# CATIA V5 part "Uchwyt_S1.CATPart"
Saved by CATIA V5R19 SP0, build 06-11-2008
Part number: Uchwyt
Bounding box of the stored display mesh (mm): x -86.292 to 86.292, y -95 to 79, z 0 to 116
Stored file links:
  G:\Catia\CD\Ustawienia\Uchwyt\Uchwyt_S1.CATPart
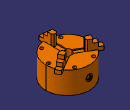
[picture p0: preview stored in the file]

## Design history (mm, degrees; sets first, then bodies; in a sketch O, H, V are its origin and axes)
Parameters
  Rozstaw = 45 mm
Body1 (main body)
  Sketch1 on xy-plane, origin (0, 0, 0), H (1, 0, 0), V (0, 1, 0)
    circle A1 centre (0, 0) radius 79
    circle A2 centre (0, 0) radius 16
    radius A1 = 79
    radius A2 = 16
  Pad1: profile Sketch1, direction (0, 0, 1), length 80
  Sketch2 on end face of Pad1, origin (55.5929, -45.085, 80), H (1, 0, 0), V (0, 1, 0)
    point P1 (-21.2096, -14.6017)
    construction line L1 (-55.5929, 134.677) -> (-55.5929, -51.2454)
    reference intersected line E1 through (-55.5929, 0) direction (0, 1) from yz-plane
    construction line L2 (-55.5929, 44.9521) -> (-10.3181, -33.4663)
    point P4 (-55.5929, 44.9521)
    angle L2 L1 = 30
    vertical: L1 V
    coincidence: E1 L1, P4 L1, P1 L2
  Hole1: placed by Sketch2, at (34.3834, -59.6867, 80) direction (0, 0, -1), diameter 8, through (limit type 6), counterbore diameter 12, counterbore depth 10
  CircPattern1: of Hole1, instances 6, angular step 60 {= 360.0*1 deg/CircPattern1.AngularNumber}, axis from end face of Pad1
  Sketch3 on end face of Pad1, origin (0, 0, 80), H (1, 0, 0), V (0, 1, 0)
    line L1 (-9, -8.5652) -> (9, -8.5652)
    line L2 (9, -8.5652) -> (9, -94.3558)
    line L3 (9, -94.3558) -> (-9, -94.3558)
    line L4 (-9, -94.3558) -> (-9, -8.5652)
    distance L4 L2 = 18
    distance L2 V = 9
    horizontal: L1 H, L3 H
    vertical: L2 V, L4 V
  Pocket1: profile Sketch3, direction (0, 0, -1), length 4
  CircPattern2: of Pocket1, instances 3, angular step 120 {= 360.0*1 deg/CircPattern2.AngularNumber}, axis from end face of Pad1
  Plane1: type Offset, Offset 79, RefPlane zx-plane
  Sketch4 on Plane1, origin (0, 79, 0), H (-1, 0, 0), V (0, 0, 1)
    circle A1 centre (0, 40) radius 8
    point P1 (0, 40)
    reference projected line E1 through (0, 0) direction (0, 1) from axis of face of Pad1 from Sketch1.A1
    distance A1 E1 = 8
    coincidence: P1 V
  Pocket2: profile Sketch4, direction (0, -1, 0), length 3
  Sketch5 on Plane1, origin (0, 79, 0), H (-1, 0, 0), V (0, 0, 1)
    circle A1 centre (0, 40) radius 12
    point P1 (0, 40)
    reference projected line E1 through (0, 0) direction (0, 1) from axis of face of Pad1 from Sketch1.A1
    distance A1 E1 = 12
    coincidence: P1 V
  Pocket3: profile Sketch5, direction (0, -1, 0), length 2
  Sketch6 on end face of Pocket2, origin (0, 76, 0), H (-1, 0, 0), V (0, 0, 1)
    point P1 (0, 40)
    point P2 (-4.348, 34.4178)
    point P3 (2.6603, 33.4434)
    point P4 (7.0083, 39.0256)
    point P5 (4.348, 45.5822)
    point P6 (-2.6603, 46.5566)
    point P7 (-7.0083, 40.9744)
    point P8 (-0.8438, 33.9306)
    line L1 (-4.348, 34.4178) -> (2.6603, 33.4434)
    line L2 (2.6603, 33.4434) -> (7.0083, 39.0256)
    line L3 (7.0083, 39.0256) -> (4.348, 45.5822)
    line L4 (4.348, 45.5822) -> (-2.6603, 46.5566)
    line L5 (-2.6603, 46.5566) -> (-7.0083, 40.9744)
    line L6 (-7.0083, 40.9744) -> (-4.348, 34.4178)
    construction line L7 (0, 40) -> (-0.8438, 33.9306)
    construction circle A1 centre (0, 40) radius 7.0758
    construction arc A2 centre (-2.6603, 46.5566) radius 7.0758 from (4.348, 45.5822) to (-7.0083, 40.9744) cw
    construction arc A3 centre (2.6603, 33.4434) radius 7.0758 from (7.0083, 39.0256) to (-4.348, 34.4178) ccw
    coincidence: P1 V, A1 P2, A1 P3, A1 P4, A1 P5, A1 P6, A1 P7, A2 P1, A3 P1
    midpoint: P8 L1
    parallelism: L1 L4
  Pocket4: profile Sketch6, direction (0, -1, 0), length 3
Body2
  Sketch7 on face of CircPattern2, origin (0, 0, 76), H (1, 0, 0), V (0, 1, 0)
    line L1 (-3.3431, -45) -> (3.3431, -45)
    line L2 (9, -50.6569) -> (9, -94.4449)
    line L3 (-9, -94.4449) -> (-9, -50.6569)
    point P1 (9, -75.6569)
    point P2 (-9, -75.6569)
    line L4 (-3.3431, -45) -> (-9, -50.6569)
    line L5 (3.3431, -45) -> (9, -50.6569)
    arc A1 centre (0, -21.7581) radius 73.2419 from (-9, -94.4449) to (9, -94.4449) ccw
    point P7 (0, -21.7581)
    angle L1 L4 = 45
    length L4 = 8
    angle L1 L5 = 45
    length L5 = 8
    distance P1 P2 = 18
    distance H L1 = 45 {= Rozstaw}
    distance A1 L1 = 50
    horizontal: L1 H
    vertical: L2 V, L3 V
    coincidence: L3, P7 V
  Pad2: profile Sketch7, direction (0, 0, 1), length 40
  Sketch8 on end face of Pad2, origin (0, 0, 116), H (1, 0, 0), V (0, 1, 0)
    arc A1 centre (0, 0) radius 65 from (-20.7552, -61.5973) to (37.7409, -52.921) ccw
    point P1 (0, 0)
    line L1 (37.7409, -52.921) -> (29.7667, -100.8266)
    arc A2 centre (-1.9378, -95.5492) radius 32.1407 from (29.7667, -100.8266) to (-33.6423, -100.8266) cw
    arc A3 centre (10.2629, -93.5184) radius 44.5093 from (-33.6423, -100.8266) to (-20.7552, -61.5973) cw
    reference projected line E1 (3.3431, -45) -> (-3.3431, -45) from edge [face of Pad2 from Sketch7.L1 | end face of Pad2]
    radius A1 = 65
    distance A1 E1 = 20
    coincidence: P1 V
    tangency: A2 L1, A3 A2
  Pocket5: profile Sketch8, direction (0, 0, -1), length 13.5
  Sketch9 on end face of Pocket5, origin (0, 0, 102.5), H (1, 0, 0), V (0, 1, 0)
    arc A1 centre (0, -15) radius 65 from (-20.7552, -76.5973) to (37.7409, -67.921) ccw
    reference projected line E1 (3.3431, -45) -> (-3.3431, -45) from edge [face of Pad2 from Sketch7.L1 | end face of Pad2]
    line L1 (37.7409, -67.921) -> (30.2023, -110.7126)
    line L2 (30.2023, -110.7126) -> (-20.7552, -110.7126)
    line L3 (-20.7552, -110.7126) -> (-20.7552, -76.5973)
    distance A1 E1 = 35
    horizontal: L2 H
    vertical: L3 V
  Pocket6: profile Sketch9, direction (0, 0, -1), length 13.5
  CircPattern3: of the body so far, instances 3, angular step 120, axis from face of Pad1 from Sketch1.A2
